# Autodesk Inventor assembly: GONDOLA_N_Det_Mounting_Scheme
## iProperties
Shininess: 64.0
Length Units: 11272
Angle Units: 11279
Time Units: 11290
Mass Units: 11286
Length Display Precision: 3
Angle Display Precision: 2
Compacted: True
Part Number: GONDOLA_N_Det_Mounting_Scheme
Document SubType Name: Assembly
Created: 2005-04
Designer: John Blackburn
Manufacturer: Standard
Standards Organization: Custom
Density: 0.0
Volumn: 0.0
Area: 0.0
PropertySet Name: Model Information
Control State: 0
Master: False
Checked Out: False
Author: John Blackburn
